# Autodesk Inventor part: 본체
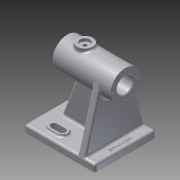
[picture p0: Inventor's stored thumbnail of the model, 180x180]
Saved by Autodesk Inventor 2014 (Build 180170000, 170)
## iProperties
Created: 2019-10
Part Number: 본체
Material: Aluminum 6061
Document SubType Name: Modeling
Designer: kh
Density: 2.71 g/cm^3
Appearance: Aluminum - Flat
Mass: 588.619 g
Surface Area: 540.35 cm^2
Volume: 217.202 cm^3
Author: kh
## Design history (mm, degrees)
sketch "Sketch1"
  geometry: L1 (-50, 43)-(50, 43); L2 (50, 43)-(50, -43); L3 (50, -43)-(-50, -43); L4 (-50, -43)-(-50, 43); L5 (-50, 43)-(50, -43); L6 (50, 43)-(-50, -43); 1 further point
  constraints: 12 end point, 2 midpoint, 2 parallel, 1 horizontal, 1 perpendicular
  dimensions: "d0" = 100 distance of L1.start L1.end; "d1" = 86 distance of L1.end L2.end
extrude "Extrusion1" new body sketch "Sketch1" distance "d2" = 10; taper "d3" = 0 deg
sketch "Sketch2"
  geometry: L1 (0, 86)-(-32, 86); L2 (-32, 86)-(-32, 107); L3 (-32, 107)-(50, 107); L4 (50, 107)-(50, 86); L5 (50, 86)-(0, 86); L6 (-50, 0)-(50, 0) reference; L7 (50, 0)-(50, 10) reference; 3 further points
  constraints: 10 end point, 2 midpoint, 2 parallel, 1 collinear, 1 horizontal, 1 perpendicular, 1 vertical alignment
  dimensions: "d4" = 42 diameter of L3 L5; "d5" = 82 distance of L2.end L3.end; "d6" = 86 distance between parallel lines of L5 L6
revolve "Revolution1" sketch "Sketch2" stored, may be unused: angle "d7" = 90 deg
sketch "Sketch3"
  geometry: L1 (-32, 65)-(-32, 107) reference; L2 (50, 65)-(50, 107) reference; L3 (-32, 65)-(50, 65) reference; L4 (-32, 86)-(-32, 100.5); L5 (30, 100.5)-(30, 97.5); L6 (30, 97.5)-(50, 97.5); L7 (50, 97.5)-(50, 86); L8 (50, 86)-(-32, 86); L9 (-32, 100.5)-(30, 100.5); 1 further point
  constraints: 12 end point, 2 midpoint, 2 parallel, 2 perpendicular, 2 point on line
  dimensions: "d8" = 23 diameter of L6 L8; "d9" = 29 diameter of L9 L8; "d10" = 62 distance between parallel lines of L5 L1
revolve "Revolution2" sketch "Sketch3" stored, may be unused: angle "d11" = 90 deg
chamfer "Chamfer1" distance "d12" = 1; stored, may be unused: second distance "d13" = 2, angle "d14" = 45 deg
sketch "Sketch4"
  geometry: L1 (24, -27)-(12, -27); L2 (24, -20)-(12, -20); L3 (12, -34)-(24, -34); L4 (50, 43)-(50, -43) reference; L5 (-50, -43)-(-50, 43) reference; L6 (50, 0)-(-50, 0); A1 r 7 centre (24, -27) between (24, -34) and (24, -20); A2 r 7 centre (12, -27) between (12, -20) and (12, -34); 2 further points
  constraints: 10 end point, 4 point on circle, 4 tangent, 3 midpoint, 2 centre point, 1 horizontal, 1 parallel
  dimensions: "d15" = 12 distance of L3.start L3.end; "d16" = 14 distance between parallel lines of L2 L3; "d17" = 27 distance between parallel lines of L6 L1; "d18" = 26 distance from line of L3.end L4
extrude "Extrusion2" join sketch "Sketch4" distance "d19" = 3; taper "d20" = 0 deg
sketch "Sketch5"
  geometry: L1 (24, -27)-(12, -27); L2 (24, -22.5)-(12, -22.5); L3 (12, -31.5)-(24, -31.5); L4 (50, -43)-(50, 43) reference; A1 r 4.5 centre (24, -27) between (24, -31.5) and (24, -22.5); A2 r 4.5 centre (12, -27) between (12, -22.5) and (12, -31.5); 2 further points
  constraints: 8 end point, 4 point on circle, 4 tangent, 2 centre point, 1 horizontal, 1 midpoint, 1 parallel
  dimensions: "d21" = 12 distance of L3.start L3.end; "d22" = 9 distance between parallel lines of L2 L3; "d23" = 26 distance from line of L3.end L4; "d24" = 27 vertical distance of point (0, 0) point (18, -27)
extrude "Extrusion3" cut sketch "Sketch5" stored distance "d25" = 3; taper "d26" = 0 deg
fillet "Fillet1" dims "d27" = 3
mirror "Mirror1"
workplane "Work Plane1"
fillet "Fillet3" dims "d30" = 3
fillet "Fillet4" dims "d31" = 3
sketch "Sketch6"
  geometry: L1 (0, 86)-(7, 86) reference; L2 (7, 0)-(0, 0) reference; L3 (7.783, 85.896)-(91.48, 63.272); L4 (91.48, 22.728)-(7.783, 0.104); L5 (7.783, 85.896)-(7.783, 0.104); A1 r 21 centre (86, 43) between (91.48, 63.272) and (91.48, 22.728) reference; A2 r 3 centre (7, 83) between (10, 83) and (7, 86) reference; A3 r 3 centre (7, 3) between (7, 0) and (10, 3) reference; A4 r 21 centre (86, 43) between (91.48, 63.272) and (91.48, 22.728); 1 further point
  constraints: 6 end point, 6 point on circle, 6 tangent, 1 centre point, 1 perpendicular
extrude "Extrusion4" join sketch "Sketch6" distance "d32" = 10; taper "d33" = 0 deg
fillet "Fillet5" dims "d34" = 3
sketch "Sketch7"
  geometry: L1 (-47, 10)-(25.104, 10) reference; L2 (-35, 10)-(-20.243, 50.546); L3 (-50, 0)-(-50, 7) reference; 1 further point
  constraints: 2 end point, 1 point on line
  dimensions: "d36" = 15 distance from line of L2.start L3; "d37" = 70 deg angle of L1 L2
feature "Rib1" sketch "Sketch7" dims "d38" = 1, "d39" = 10, "d40" = 0, "d41" = 0, "d42" = 1, "d43" = 1
fillet "Fillet7" dims "d44" = 3
fillet "Fillet8" dims "d45" = 3
sketch "Sketch8" dims "d46" = 36
  geometry: C1 r 21 at (0, 0) reference; 3 further points
  constraints: 2 vertical alignment, 1 coincident, 2 other
hole "Hole1" sketch "Sketch8" at (0, 18) diameter "d47" = 2.459; stored, may be unused: countersink angle "d51" = 90 deg, drill point angle "d53" = 118 deg; dims "d48" = 8, "d49" = 4, "d50" = 2, "d52" = 10
pattern_circular "Circular Pattern1" dims angle "d55" = 360 deg
sketch "Sketch9" dims "d57" = 36
  geometry: C1 r 21 at (0, 0) reference; 3 further points
  constraints: 2 vertical alignment, 1 coincident, 2 other
hole "Hole2" sketch "Sketch9" at (0, 18) diameter "d58" = 2.459; stored, may be unused: countersink angle "d62" = 90 deg, drill point angle "d64" = 118 deg; dims "d59" = 8, "d60" = 4, "d61" = 2, "d63" = 10
pattern_circular "Circular Pattern2" dims angle "d66" = 360 deg
workplane "Work Plane2"
sketch "Sketch10"
  geometry: L1 (32, 21)-(32, -21) reference; L2 (32, 21)-(-50, 21) reference; C1 r 11 at (7, 0); 1 further point
  constraints: 1 centre point, 1 horizontal alignment
  dimensions: "d69" = 22 diameter of C1; "d70" = 25 distance from line of C1.centre L1
extrude "Extrusion5" join sketch "Sketch10" stored distance "d71" = 10; taper "d72" = 0 deg
sketch "Sketch11"
  geometry: C1 r 11 at (0, 0) reference; 2 further points
  constraints: 1 coincident
hole "Hole3" sketch "Sketch11" at (0, 0) diameter "d73" = 4.917; stored, may be unused: countersink angle "d77" = 90 deg, drill point angle "d79" = 118 deg; dims "d74" = 8, "d75" = 14, "d76" = 4, "d78" = 10
fillet "Fillet9" dims "d80" = 3
fillet "Fillet10" dims "d81" = 3
workplane "Work Plane3"
sketch "Sketch12"
  geometry: L1 (-40.598, 16.592)-(-40.598, -16.592); L2 (-40.598, -16.592)-(-45.402, -16.592); L3 (-45.402, -16.592)-(-45.402, 16.592); L4 (-45.402, 16.592)-(-40.598, 16.592); L5 (-40.598, 16.592)-(-45.402, -16.592); L6 (-40.598, -16.592)-(-45.402, 16.592); L7 (-50, 40)-(-50, -40) reference; L8 (47, 43)-(-47, 43) reference; 2 further points
  constraints: 4 end point, 1 midpoint, 2 other
  dimensions: "d83" = 7 distance from line of L7 point (-43, 0); "d84" = 43 distance from line of L8 point (-43, 0)
emboss "Emboss1" sketch "Sketch12" dims "d0" = 100, "d1" = 86, "d85" = 0.5, "d86" = 0
body "Solid1"
node "Projected Loop1"
other parameters: "d29" = -15, "d82" = 7
